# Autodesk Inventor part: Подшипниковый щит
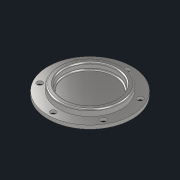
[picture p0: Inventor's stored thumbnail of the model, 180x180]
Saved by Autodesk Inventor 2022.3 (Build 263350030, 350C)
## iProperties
Created: 2022-08
Part Number: Подшипниковый щит
Material: Сталь 40ХНМА
Document SubType Name: Modeling
Designer: Карташов
Density: 7.85 g/cm^3
Appearance: С умеренной полировкой
Author: Карташов
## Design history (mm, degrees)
sketch "Эскиз1"
  geometry: L1 (0, 0)-(0, 34.001); L2 (30, 0)-(60, 0); L3 (60, 0)-(60, 5); L4 (60, 5)-(45, 5); L5 (45, 5)-(45, 12); L6 (43, 14)-(39, 14); L7 (37, 12)-(37, 7); L8 (35, 5)-(0, 5); L9 (30, 0)-(28, -2); L10 (28, -2)-(0, -2); L11 (0, -2)-(0, 0); A1 r 2 centre (35, 7) between (35, 5) and (37, 7); A2 r 2 centre (43, 12) between (45, 12) and (43, 14); A3 r 2 centre (39, 12) between (39, 14) and (37, 12); 3 further points
  constraints: 22 end point, 6 point on circle, 6 tangent, 5 horizontal, 5 point on line, 3 centre point, 3 vertical, 2 perpendicular, 1 horizontal alignment, 1 midpoint
  dimensions: "d0" = 90 diameter of L5 point (0, 17); "d1" = 120 diameter of L3 L1; "d3" = 14 vertical distance of L2.end point (45, 14); "d4" = 5 distance of L2.end L3.end; "d5" = 9 distance between parallel lines of L8 L6; "d6" = 8 distance of point (45, 14) point (37, 14); "d7" = 2 radius of A1; "d21" = 2 horizontal distance of L2.start L9.end; "d22" = 2 horizontal distance of L2.start L9.end; "d23" = 60 diameter of L2.start L1; "d24" = 2 radius of A2; "d25" = 2 radius of A3 (derived)
revolve "Вращение1" sketch "Эскиз1" stored, may be unused: angle "d9" = 90 deg
sketch "Эскиз2"
  geometry: C1 r 45 at (0, 0) reference; C2 r 60 at (0, 0) reference; 2 further points
  constraints: 1 vertical alignment
  dimensions: "d10" = 52.5 distance of point (0, 0) point (0, -52.5)
  node "Спроецированная петля1"
sketch "Эскиз3"
  geometry: 2 further points
hole "Отверстие1" sketch "Эскиз3" at (0, 52.5) diameter "d11" = 8; stored, may be unused: countersink angle "d15" = 90 deg, drill point angle "d17" = 0 deg; dims "d12" = 6, "d13" = 13, "d14" = 1, "d16" = 22.5
pattern_circular "Круговой массив1" dims angle "d19" = 360 deg
node "Твердое тело1"
